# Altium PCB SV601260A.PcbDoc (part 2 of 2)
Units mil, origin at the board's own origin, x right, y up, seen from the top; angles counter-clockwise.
Board outline 2250 x 2132 mil, 4 copper layers (Top Layer, GND, POWER, Bottom Layer), stack 59.6 mil thick; 105 components, 61 nets, 262 pads, 157 vias.
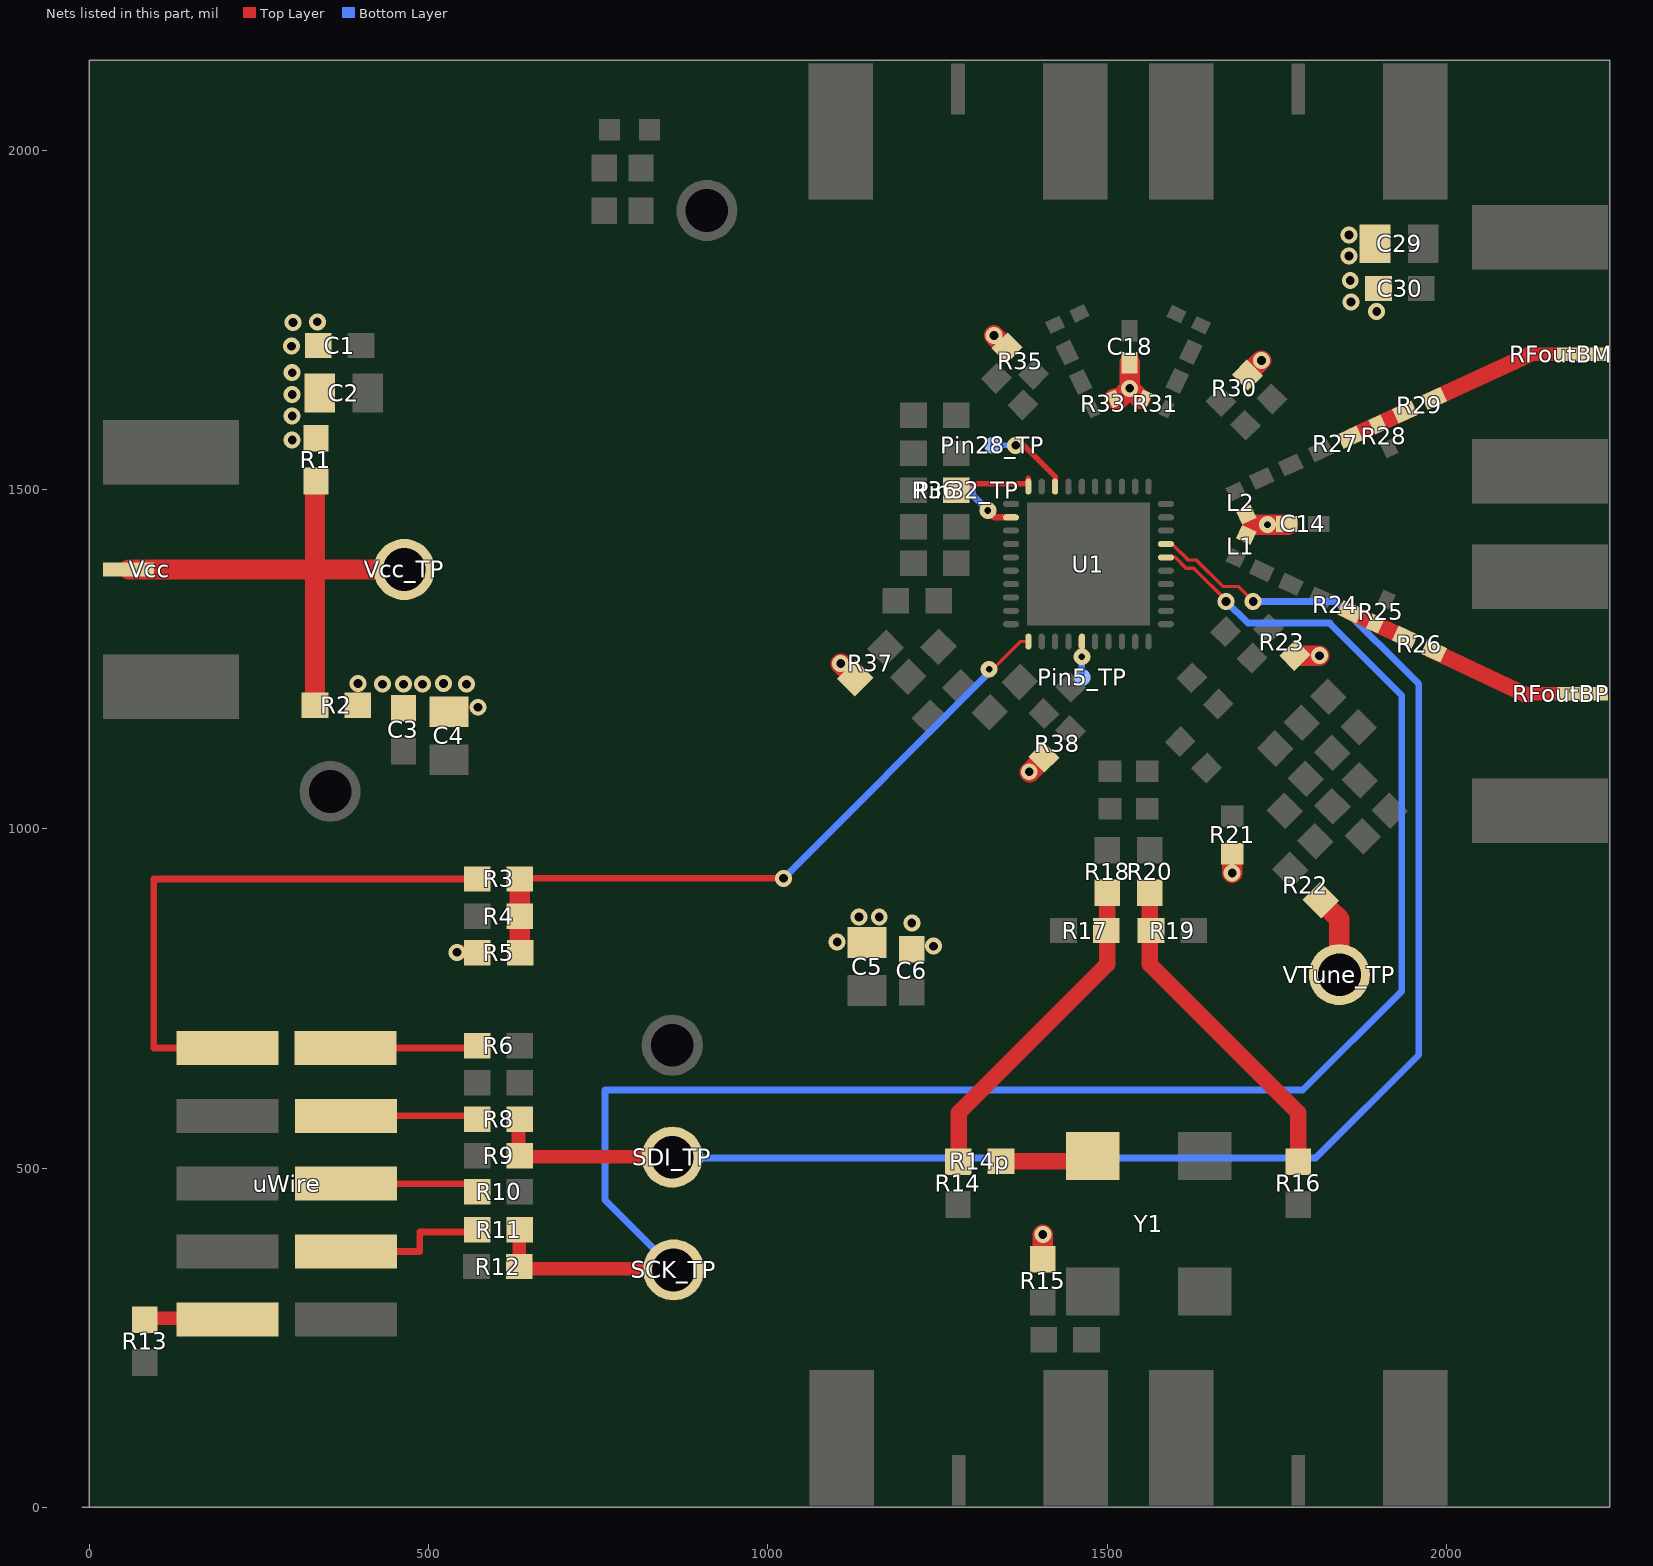
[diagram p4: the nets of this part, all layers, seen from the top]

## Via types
v1: diameter 25, hole 13, Top Layer to Bottom Layer, tented both sides, 74 vias
v2: diameter 25, hole 13, Top Layer to Bottom Layer, 65 vias
v3: diameter 19.68, hole 7.87, Top Layer to Bottom Layer, 12 vias
v4: diameter 25, hole 10, Top Layer to Bottom Layer, 6 vias

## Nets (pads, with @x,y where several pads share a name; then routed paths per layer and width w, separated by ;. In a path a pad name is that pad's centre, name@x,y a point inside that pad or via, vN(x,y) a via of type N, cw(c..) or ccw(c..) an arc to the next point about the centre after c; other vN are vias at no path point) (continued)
NetPin5_TP_1: Pin5_TP.1 U1.5 | length 46.4
  Top Layer w10: v4(1462.44,1253.44) U1.5@1462.44,1275.83
  Bottom Layer w10: Pin5_TP.1@1462.44,1229.44 v4(1462.44,1253.44)
NetPin28_TP_1: Pin28_TP.1 U1.28 | length 125.9
  Top Layer w8: v1(1365,1565) 1377,1565 1423.07,1518.93 U1.28@1423.07,1504.17
  Bottom Layer w8: Pin28_TP.1@1331,1565 v1(1365,1565)
NetPin32_TP_1: Pin32_TP.1 U1.32 | length 80.7
  Top Layer w10: v4(1324,1469) 1334.1,1458.9 U1.32@1358.11,1458.9
  Bottom Layer w10: Pin32_TP.1@1294,1499 v4(1324,1469)
NetR1_1: R1.1 R2.1 Vcc.1 Vcc_TP.1 | length 735
  Top Layer w30: Vcc.1@58,1382 332.5,1382 ; R2.1@332.5,1182 332.5,1382 ; R1.1@332.5,1511.01 332.5,1382 ; Vcc_TP.1@464,1382 332.5,1382
NetR3_1: R3.1 uWire.1 | length 833
  Top Layer w10: 95,677 uWire.1@203.5,677 ; 95,678 95,926 R3.1@571.5,926
NetR3_2: R3.2 R4.2 R5.2 U1.1 | length 1005.3
  Top Layer w5: v4(1326,1235) 1331,1235 1371.83,1275.83 U1.1@1383.7,1275.83 U1.1@1383.53,1276
  Top Layer w10: R3.2@634.5,926 635.5,927 v2(1023,927)
  Top Layer w30: R5.2@634.5,818 R4.2@634.5,871 R3.2@634.5,926
  Bottom Layer w10: v2(1023,927) 1326,1230 v4(1326,1235)
NetR6_1: R6.1 uWire.2 | length 194
  Top Layer w10: uWire.2@377.5,677 R6.1@571.5,677
NetR8_1: R8.1 R9.2 SDI_TP.1 U1.17 | length 2427.2
  Top Layer w5: U1.17@1586.46,1419.53 1595.47,1419.53 1619,1396 1631.4,1396 1670.4,1357 1693,1357 v1(1715,1335)
  Top Layer w20: 632.5,553 632.5,517 826,517 SDI_TP.1@844,499
  Bottom Layer w10: SDI_TP.1@860,500 875,515 1807,515 1959,667 1959,1213 1837,1335 v1(1715,1335)
NetR8_2: R8.2 uWire.4 | length 192
  Top Layer w10: uWire.4@378.5,577 R8.2@570.5,577
NetR10_2: R10.2 uWire.6 | length 202.5
  Top Layer w10: uWire.6@378.5,477 R10.2@581,477
NetR11_1: R11.1 uWire.8 | length 222
  Top Layer w10: uWire.8@378.5,377 487,377 487,406 R11.1@571.5,406
NetR11_2: R11.2 R12.2 SCK_TP.1 U1.16 | length 2691.2
  Top Layer w5: U1.16@1586.46,1399.84 1600.16,1399.84 1616,1384 1627.3,1384 1675,1336.3 v1(1675,1335)
  Top Layer w20: R11.2@634.5,409 633.5,408 R12.2@633.5,355 636.5,352 SCK_TP.1@861,352
  Bottom Layer w10: SCK_TP.1@861,352 760,453 760,615 1788,615 1934,761 1934,1196 1827,1303 ; v1(1675,1335) 1707,1303 1828,1303
NetR13_1: R13.1 uWire.9 | length 107.5
  Top Layer w20: R13.1@82,278.91 uWire.9@189.5,278.41
NetR14_2: R14.2 R14p.1 R17.1 R18.1 | length 485.2
  Top Layer w24: R14p.1@1281.34,510.83 1281.34,581.66 1500,800.32 R18.1@1500,905.5
NetR14p_2: R14p.2 Y1.3 | length 138.1
  Top Layer w24: R14p.2@1343.5,510 1470.32,510 Y1.3@1478.32,518
NetR16_2: R16.2 R19.2 R20.2 | length 485.2
  Top Layer w24: R20.2@1562.68,905.5 1562.68,800.32 1781.34,581.66 R16.2@1781.34,510.83
NetR22_2: R22.2 VTune_TP.1 | length 98.5
  Top Layer w30: 1830.31,878.69 1842,867 VTune_TP.1@1842,785
NetR24_1: R24.1 R25.2 R26.2 | length 85.5
  Top Layer w24: R24.1@1855,1321 R26.2@1932.37,1284.51
NetR26_1: R26.1 RFoutBP.1 | length 235.1
  Top Layer w20: 2118.03,1199.06 RFoutBP.1@2200,1199.06
  Top Layer w24: R26.1@1978.06,1262.84 1981.12,1261.39 2116.51,1197.54
NetR27_1: R27.1 R28.1 R29.2 | length 85.5
  Top Layer w24: R27.1@1860,1578 R29.2@1937.68,1613.81
NetR29_1: R29.1 RFoutBM.1 | length 229.8
  Top Layer w20: 2123.25,1699.06 RFoutBM.1@2200,1699.06
  Top Layer w24: R29.1@1981.41,1633.98 2120.43,1698.07
NetR36_1: R36.1 U1.30 | length 105.8
  Top Layer w8: R36.1@1286,1508.17 1383.7,1508.17 1383.7,1516.3
VCC: C3.2 C4.2 C5.2 C6.2 R2.2 R5.1 R15.2 R21.1 R23.1 R35.2 R37.2 R38.1 | length 192.7
  Top Layer w20: v2(542,818) R5.1@571.5,818
  Top Layer w30: v1(1107.16,1243.3) R37.2@1128.73,1221.73 ; v1(1333,1727) R35.2@1351.51,1708.49 ; v1@1385.5,1083.5 R38.1@1404.46,1102.46 ; R15.2@1405,365.5 v2(1405,402) ; v1(1684,935) v1@1684,944.69 ; R23.1@1779,1255 v2(1812.5,1255)
  other v1: 1385,1084 463,1213 556,1213 396,1214 522,1214
  other v2: 1244,827 1102,833 1212,861 1134,870 1164,870 573,1179 432,1213 491,1213
VCCRF: C1.2 C2.2 C14.2 C18.2 C29.2 C30.2 L1.2 L2.2 R1.2 R30.1 R31.2 R33.1 | length 170.4
  Top Layer w30: R33.1@1510.06,1633.49 1517.49,1633.49 v2(1533,1649) ; C18.2@1533,1686.38 v2(1533,1649) ; R31.2@1548.51,1633.49 v2(1533,1649) ; R30.1@1705.99,1668.99 v1(1727,1690) ; 1714,1448 C14.2@1766,1448
  other v1: 299,1573 299,1608 299,1640 298,1711
  other v2: 299,1672 300,1746 336,1747 1897,1762 1859,1776 1858,1808 1856,1844 1856,1875
  other v4: 1736,1448
pads on no net: uWire.5 uWire.7 uWire.10 Y1.1

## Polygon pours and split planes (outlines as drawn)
GND on Top Layer "Top Layer-No Net 1" (solid, pour order 11): 1943,1888.52 1944,1887.36 1944,1746 2023,1746 2019,1750.64 2019,1890.84 1944,1890.84 1943,1892
VCCRF on Top Layer "Top Layer-No Net 1" (solid, pour order 10): 1840,1888.55 1841.01,1887.4 1841.01,1747 1921,1747 1916.95,1751.6 1916.95,1890.85 1841.01,1890.85 1840,1892
GND on Top Layer "Top Layer-No Net 2" (solid, pour order 13): 1088,784 1261,784 1261,715.06 1258.49,713 1090.51,713 1088,715.06 1088,781.94
VCC on Top Layer "Top Layer-No Net 2" (solid, pour order 12): 1088,884 1258,884 1258,812.14 1255.54,810 1090.46,810 1088,812.14 1088,881.86
VCCRF on Top Layer "Top Layer-No Net 3" (solid, pour order 14): 362,1557.2 287,1557.2 286,1556 276,1567.97 276,1763 356,1763 358,1760.61 362,1755.82 362,1558.39
GND on Top Layer "Top Layer-No Net 4" (solid, pour order 15): 381,1761 381,1616.85 383,1614.32 388,1608 465,1608 465,1761 381,1761
GND on Top Layer "Top Layer-No Net" (solid, pour order 17): 557,1133 305,1133 309,1129 309,1000 561,1000 560,1001 560,1133 556,1133 555,1132
VCC on Top Layer "Top Layer-No Net 5" (solid, pour order 18): 582.56,1151 377.29,1151 376.15,1150 376.15,1226 375,1227 586,1227 586,1150
GND on Top Layer "VCOGND" (solid, pour order 16): 1301,1713 1088,1713 999,1624 999,1170 1115,1054 1232,1054 1235,1054 1334,1153 1296,1191 1252,1191 1252,1192 1199.5,1244.5 1167,1212 1167,1211 1167,1187 1122,1142 1056,1208 1056,1244 1130,1318 1208,1318 1208,1357 1223,1372 1233,1372 1233,1645 1334,1645 1335,1646 1336,1647 1336,1678 1301,1713
GND on GND (split plane): 2239.95,0.05 0.05,0.05 0.05,2131.95 2239.95,2131.95
VCCRF on POWER (split plane): 2219.9,1280.09 2069.18,1280.09 1957.13,1392.13 1952.13,1397.13 1950.04,1398.74 1947.61,1399.74 1945,1400.09 1734.18,1400.09 1701.09,1433.18 1701.09,1539 1700.74,1541.61 1700.03,1543.33 1699.74,1544.04 1698.13,1546.13 1657.13,1587.13 1655.04,1588.74 1652.61,1589.74 1650,1590.09 1564.18,1590.09 1457.13,1697.13 1232.13,1922.13 1230.04,1923.73 1227.61,1924.74 1225,1925.09 710,1925.09 707.39,1924.74 706.17,1924.24 704.96,1923.73 702.87,1922.13 637.87,1857.13 636.27,1855.04 635.26,1852.61 634.91,1850 634.91,1795 634.91,1760 634.91,1609.18 616.87,1591.13 612.87,1587.13 577.82,1552.09 20.1,1552.09 20.1,2111.9 2219.9,2111.9
VCC on POWER (split plane): 1442.87,1682.87 1552.87,1572.87 1554.96,1571.26 1557.39,1570.26 1560,1569.91 1645.82,1569.91 1680.91,1534.82 1680.91,1429 1681.26,1426.39 1682.26,1423.96 1683.87,1421.87 1722.87,1382.87 1724.96,1381.26 1726.68,1380.55 1727.39,1380.26 1730,1379.91 1940.82,1379.91 1942.87,1377.87 2057.87,1262.87 2059.96,1261.26 2060.67,1260.97 2062.39,1260.26 2065,1259.91 2219.9,1259.91 2219.9,20.1 20.1,20.1 20.1,1531.91 582,1531.91 584.61,1532.26 587.04,1533.26 589.13,1534.87 631.13,1576.87 652.13,1597.87 653.73,1599.96 654.45,1601.68 654.74,1602.39 655.09,1605 655.09,1760 655.09,1795 655.09,1845.82 714.18,1904.91 1220.82,1904.91

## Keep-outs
Keep-Out Layer:
  lines w1: 0,0 2238,0 2240,0 2240,2132 0,2132 0,195 ; 0,0 0,195 ; 0,0 0,195
  text ".Layer_Name" at 327,-1618.49 h60

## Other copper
Top Layer:
  text ".Layer_Name" at 327,-1618.49 h60
Bottom Layer:
  text ".Layer_Name" at 327,-1618.49 h60
POWER (plane layer: these items are gaps in the copper):
  lines w20: 0,1542 465,1542 ; 462,1542 582,1542 624,1584 ; 620,1580 645,1605 645,1760 645,1795 645,1850 710,1915 1070,1915 1120,1915 ; 1110,1915 1225,1915 1450,1690 1560,1580 1650,1580 1691,1539 1691,1429 1730,1390 1945,1390 1950,1385 2065,1270 2100,1270 2236,1270

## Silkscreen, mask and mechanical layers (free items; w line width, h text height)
Top Overlay:
  circle w20: c1311.93,1264 r7.07
  region: 84,2015 34,2015 34,1963 84,1963
  region: 85,2093 35,2093 35,2041 85,2041
  region: 371,1880 254,1880 254,1828 371,1828
  lines w5: 91.5,513.5 121.68,543.68 ; 109.68,543.68 121.68,543.68 ; 121.68,528.32 121.68,543.68
  text "LMX2582EVM" at 105,2040 h60
  text "LMX2592EVM" at 104,1959 h60
  text "12-18-2015" at 79,1904 h25
  text "Board #" at 51,1851 h25
  text "CE" at 61,678 h25
  text "MUXout" at 57,592 h25 r270
  text ".Layer_Name" at 327,-1618.49 h60
Bottom Overlay:
  rectangle: 413,33 713,133
  text "Rev A" at 970,120 h25
  text "SV601260-" at 983,67 h30
  text ".Layer_Name" at 327,-1618.49 h60
Top Paste:
  text ".Layer_Name" at 327,-1618.49 h60
Bottom Paste:
  text ".Layer_Name" at 327,-1618.49 h60
Top Solder:
  lines w40: 1278,2052 1278,2121 ; 1279.12,2048.59 1511.99,1549.18 ; 1530.45,1507.2 1530.45,1541.2 ; 1552.27,1551.77 1779.49,2039.04 ; 1609.94,1465.12 2117.3,1699.1 ; 1610.68,1431.48 2116.4,1200 ; 1783,2047 1783,2116 ; 2115,1200 2233,1200 ; 2120,1700 2236,1700
  text ".Layer_Name" at 327,-1618.49 h60
  text ".Layer_Name" at 327,-1618.49 h60
Bottom Solder:
  text ".Layer_Name" at 327,-1618.49 h60
Drill Guide:
  text ".Layer_Name" at 327,-1618.49 h60
M1 Board Outline:
  lines w5: -1,0 2239,0 ; -1,2131 2240,2131 2240,0
  text ".Layer_Name" at 327,-1618.49 h60
M2 Board Dimensions:
  rectangle: -125.5,-1170.5 249.5,-1045.5
  rectangle: -250.5,-1045.5 -125.5,-920.5
  lines w7: -250.5,-1045.5 749.5,-1045.5 ; -125.5,-1170.5 -125.5,-920.5 ; -0.5,-1170.5 -0.5,-920.5 ; 249.5,-1170.5 249.5,-920.5 ; 499.5,-1170.5 499.5,-920.5 ; -250.5,-1170.5 -250.5,-920.5 749.5,-920.5 749.5,-1170.5 -250.5,-1170.5
  lines w10: -250.5,-1235.5 -250.5,-1215.5 ; -190.5,-1245.5 -250.5,-1225.5 ; -190.5,-1205.5 -250.5,-1225.5 ; -26.42,-1225.5 -250.5,-1225.5 ; 525.42,-1225.5 749.5,-1225.5 ; 689.5,-1245.5 749.5,-1225.5 ; 689.5,-1205.5 749.5,-1225.5 ; 749.5,-1235.5 749.5,-1215.5
  text "1000 (mil)" at -16.42,-1261.49 h60
  text ".Layer_Name" at 327,-1618.49 h60
M3 3D STEP Top:
  text ".Layer_Name" at 327,-1618.49 h60
M4 3D STEP Bottom:
  text ".Layer_Name" at 327,-1618.49 h60
M5 Assembly Top:
  lines w10: -542,-1690.17 6058,-1690.17 ; -542,-1486.83 6060,-1486.83 ; -542,-1283.5 -542,-1893.5 3463,-1893.5 6060,-1893.5 6060,-1283.5 -541.5,-1283.5 -541.5,-1893.5 1034,-1893.5 ; 1923,-1893.5 1923,-1283.5 ; 3190,-1486.83 3190,-1283.5 ; 4030,-1486.83 4030,-1283.5 ; 4652,-1900 4652,-1697.17
  text "COMPONENTS MARKED 'DNP' SHOULD NOT BE POPULATED." at 903.5,-1078.5 h20
  text "ASSEMBLY VARIANT:" at 903,-1194 h20
  text ".VariantName" at 1939,-1194 h20
  text "PCB VIEWED FROM TOP SIDE" at -478.5,-1415.67 h60
  text "BOARD #:" at 1998,-1415.67 h60
  text ".PRJ_Number" at 2543.5,-1415.67 h60
  text "REV:" at 3388,-1415.67 h60
  text ".PCB_Rev" at 3679.5,-1415.67 h60
  text "SVN REV:" at 4226,-1415.67 h60
  text ".VersionControl_RevNumber" at 4732,-1415.67 h60
  text "TID #:" at 1998,-1619 h60
  text ".TID" at 2543.5,-1619 h60
  text "PLOT NAME =" at -478.5,-1824.34 h60
  text ".plot_File_Name" at 327,-1824.34 h60
  text "GENERATED    :" at 2000,-1824.34 h60
  text ".Print_Date" at 2869.5,-1824.34 h60
  text ".Print_Time" at 3598.5,-1824.34 h60
  text "TEXAS INSTRUMENTS" at 4863,-1824.34 h60
M6 Assembly Bottom:
  lines w10: -542.5,-1487.33 6059.5,-1487.33 ; -540.5,-1690.67 6059.5,-1690.67 ; 865.5,-1900.5 865.5,-1697.67 ; 1487.5,-1487.33 1487.5,-1284 ; 2327.5,-1487.33 2327.5,-1284 ; 3594.5,-1894 3594.5,-1284 ; 4483.5,-1894 6059,-1894 6059,-1284 -542.5,-1284 -542.5,-1894 2054.5,-1894 6059.5,-1894 6059.5,-1284
  text "COMPONENTS MARKED 'DNP' SHOULD NOT BE POPULATED." at 5852,-1078 h30
  text ".VariantName" at 4808,-1194 h30
  text "ASSEMBLY VARIANT:" at 5847,-1194 h30
  text ".VersionControl_RevNumber" at 785.5,-1416.17 h60
  text "SVN REV:" at 1291.5,-1416.17 h60
  text ".PCB_Rev" at 1838,-1416.17 h60
  text "REV:" at 2129.5,-1416.17 h60
  text ".PRJ_Number" at 2974,-1416.17 h60
  text "BOARD #:" at 3519.5,-1416.17 h60
  text "PCB VIEWED FROM BOTTOM SIDE" at 5996,-1416.17 h60
  text ".TID" at 2974,-1619.5 h60
  text "TID #:" at 3519.5,-1619.5 h60
  text "TEXAS INSTRUMENTS" at 654.5,-1824.84 h60
  text ".Print_Time" at 1919,-1824.84 h60
  text ".Print_Date" at 2648,-1824.84 h60
  text "GENERATED    :" at 3517.5,-1824.84 h60
  text ".plot_File_Name" at 5190.5,-1824.84 h60
  text "PLOT NAME =" at 5996,-1824.84 h60
M9 Title Sheet:
  drawing of 57 lines, arcs and shapes, not listed
  text "1" at 489.84,7276.5 h70
  text "2" at 2985.5,7276.5 h70
  text "3" at 5474.84,7276.5 h70
  text "4" at 7981.51,7276.5 h70
  text "5" at 10480.5,7276.5 h70
  text "6" at 12985.5,7276.5 h70
  text "A" at -666.5,6133.5 h70
  text "A" at 14133.5,6133.5 h70
  text "B" at -666.5,3753.5 h70
  text "B" at 14133.5,3753.5 h70
  text "C" at -666.5,1378.5 h70
  text "C" at 14133.5,1378.5 h70
  text "PROJECT TITLE:" at 11093.5,-482.5 h45
  text ".PRJ_Title" at 11143.5,-615.83 h70
  text "DESIGNED FOR:" at 11093.5,-783.5 h45
  text ".PRJ_Customer" at 11143.5,-923.5 h70
  text "D" at -666.5,-991.5 h70
  text "D" at 14133.5,-991.5 h70
  text "FILE NAME:" at 11093.5,-1083.5 h45
  text ".PCB_File_Name_No_Path" at 11143.5,-1203.5 h70
  text "Texas Instruments (TI) and/or its licensors do not warrant the accuracy or completeness of this specification" at 6124,-1365.34 h45
  text "ENGINEER:" at 11093.5,-1373.5 h45
  text "LAYOUT BY:" at 12598.5,-1373.5 h45
  text "or any information contained therein. TI and/or its licensors do not warrant that this design will meet" at 6079.01,-1478 h45
  text ".PRJ_Engineer" at 11143.5,-1528.49 h70
  text ".PCB_Layout" at 12649,-1528.49 h70
  text "the specifications, will be suitable for your application or fit for any particular purpose, or will operate in" at 6079.01,-1590.67 h45
  text ".Layer_Name" at 327,-1618.49 h60
  text "ALTIUM DESIGNER VERSION:" at 12598.5,-1683.5 h45
  text "an implementation. TI and/or its licensors do not warrant that the design is production worthy. You should" at 6079.01,-1703.33 h45
  text "completely validate and test your design implementation to confirm the system functionality for your application." at 6124,-1816 h45
  text ".print_Scale" at 11143.5,-1816.83 h70
  text ".Application_BuildNumber" at 12649,-1816.83 h70
  text "1" at 489.84,-2023.5 h70
  text "2" at 2985.5,-2023.5 h70
  text "3" at 5474.84,-2023.5 h70
  text "4" at 7981.51,-2023.5 h70
  text "5" at 10480.5,-2023.5 h70
  text "6" at 12985.5,-2023.5 h70
M10 Fab Notes:
  drawing of 214 lines, arcs and shapes, not listed
  text "DESIGN INFORMATION" at 12134.02,6047 h60
  text "(REFER ALSO ARRAY/PANEL PROFILING INFORMATION)" at 11772.46,5885.29 h60
  text "BOARD SIZE" at 11086.46,5881 h60
  text "2450MIL" at 11548.78,5753.18 h60
  text "X" at 12054.46,5753.18 h60
  text "2700MIL" at 12285.78,5753.18 h60
  text "Number of Layers :" at 11489.46,5556 h60
  text "4" at 12584.27,5546 h60
  text "20mils width on top layer should be controlled 50 ohms +/- 5%" at 4866,5502 h100
  text "MIN. TRACK WIDTH:" at 11489.46,5417 h60
  text "5" at 12585.7,5417 h60
  text "MIL" at 12740.46,5417 h60
  text "MIN. CLEARANCE:" at 11489.46,5285 h60
  text "5" at 12585.7,5285 h60
  text "MIL" at 12740.46,5285 h60
  text "MIN. VIA PAD SIZE:" at 11489.46,5153 h60
  text "25" at 12555.71,5153 h60
  text "MIL" at 12740.46,5153 h60
  text "0.05mm (2MIL)" at 12184.46,5011.29 h60
  text "MINIMUM ANNULAR RING" at 11160.23,5007 h60
  text "EXTERNAL" at 12892.46,5007 h60
  text "PER" at 11360.23,4889 h60
  text "IPC-D-275 CLASS 2 LEVEL C" at 11580.23,4889 h60
  text "MIL, HOLES" at 13068.46,4776.71 h60
  text "+/-" at 12676,4776 h60
  text "+/-" at 13530,4776 h60
  text "REGISTRATION TOLERANCES:" at 11160.23,4771 h60
  text "METAL" at 12360,4771 h60
  text "5" at 12936.2,4771 h60
  text "3" at 13769.2,4771 h60
  text "MIL" at 13885.46,4771 h60
  text "MATERIAL:" at 11125.46,4631.54 h60
  text "FR4 High Tg" at 12111.9,4491.21 h60
  text "X" at 12851,4484 h60
  text "FR-408" at 11546.46,4482.64 h60
  text "RO4003C" at 13034.46,4482.64 h60
  text "62 MIL (1.6mm) +/-10%" at 11866.56,4319.92 h60
  text "THICKNESS:" at 11200.23,4315.64 h60
  text "X" at 11738.4,4315.64 h60
  text "OTHER" at 13151.46,4315.64 h60
  text "TOLERANCE:" at 11200.23,4157.64 h60
  text "X" at 12039.53,4157.64 h60
  text "ANSI IPC-6012 TYPE 3 CLASS 2" at 12226.48,4157.64 h60
  text "OTHER +/-" at 12226.46,4001.64 h60
  text "BOW & TWIST:" at 11200.23,3844.64 h60
  text "X" at 12039.53,3844.64 h60
  text "ANSI IPC-6012 TYPE 3 CLASS 2" at 12226.48,3844.64 h60
  text "OTHER +/-" at 12226.46,3686.13 h60
  text "COPPER THICKNESS (FINISHED):" at 11125.46,3550.64 h60
  text "1.4MIL (1oz)" at 12005.46,3397.92 h60
  text "2MIL (1.4oz)" at 12772.46,3397.92 h60
  text "2.8MIL (2oz)" at 13499.46,3397.92 h60
  text "OUTER:" at 11482.46,3393.64 h60
  text "X" at 11877,3393 h60
  text "1.4MIL (1oz)" at 12005.46,3240.92 h60
  text "2.8MIL (2oz)" at 12772.46,3240.92 h60
  text "N/A" at 13499,3241.29 h60
  text "INNER SIGNAL:" at 11193.38,3236.64 h60
  text "X" at 11878.42,3236.64 h60
  text "DRILLING:" at 11125.46,3097.64 h60
  text "REFERENCE:" at 11200.23,2980.64 h60
  text "X" at 11848.46,2980.64 h60
  text "AS SHOWN" at 12035.46,2980.64 h60
  text "X" at 12749.46,2980.64 h60
  text "NC_DRILL FILES" at 12886.46,2980.64 h60
  text "PTH MIN COPPER THICKNESS:" at 11200.23,2822.64 h60
  text "X" at 12550.46,2822.64 h60
  text "1MIL" at 12687.46,2822.64 h60
  text "OTHER" at 13184.46,2822.64 h60
  text "BOARD FINISH:" at 11125.46,2663.64 h60
  text "SILKSCREEN:" at 11280.68,2545.64 h60
  text "X" at 12229.46,2545.64 h60
  text "TOP" at 12355.46,2545.64 h60
  text "X" at 12739.46,2545.64 h60
  text "BOTTOM" at 12866.46,2545.64 h60
  text "SILKSCREEN COLOR:" at 11280.68,2378.64 h60
  text "X" at 12228.42,2378.64 h60
  text "WHITE" at 12355.46,2378.64 h60
  text "OTHER" at 12866.46,2378.64 h60
  text "SOLDER RESIST COLOR:" at 11280.68,2208.64 h60
  text "X" at 11833.42,2069.44 h60
  text "GREEN" at 11960.46,2069.44 h60
  text "BLUE" at 12551.46,2069.44 h60
  text "OTHER" at 13089.46,2069.44 h60
  text "IMMERSION GOLD (ENIG)" at 12176.46,1915.92 h60
  text "ENEPIG" at 13514,1912.64 h60
  text "SURFACE FINISH:" at 11115.46,1911.64 h60
  text "X" at 11989.51,1911.64 h60
  text "IMM. TIN/SILVER OR EQUIV" at 11445,1754.64 h60
  text "OTHER" at 12876.46,1754.64 h60
  text "ARRAY/PANEL:" at 11115.46,1575.64 h60
  text "CUT AND TRIM PER MECH LAYER 1" at 12176.46,1571.35 h60
  text "N.C. ROUTE" at 12176.46,1419.64 h60
  text "X" at 12855.46,1419.64 h60
  text "V. SCORE" at 13042.46,1419.64 h60
  text "CERTIFICATION:" at 11115.46,1282.64 h60
  text "MATERIALS AND WORKMANSHIP FOR ALL PCBS" at 11840.46,1282.64 h60
  text "TO MEET OR EXCEED THE REQUIREMENTS OF:" at 11840.46,1184.64 h60
  text "X" at 11466.96,1048.13 h60
  text "ANSI IPC-A-600F CLASS ->" at 11605.96,1048.13 h60
  text "X" at 13245.02,1048.13 h60
  text "2" at 13363.96,1048.14 h60
  text "1" at 13048.96,1046.64 h60
  text "3" at 13717.96,1046.64 h60
  text "X" at 11469.02,888.64 h60
  text "UL 94V-0" at 11605.96,888.64 h60
  text "X" at 12281.02,888.64 h60
  text "RoHS" at 12417.96,888.64 h60
  text "OTHER" at 13062.36,888.64 h60
  text "PER ORDER" at 13459.42,888.64 h60
  text "ADDITIONAL REQUIREMENTS:" at 11115.46,732.64 h60
  text "MICROSECTION:" at 11200.23,602.64 h60
  text "YES" at 12105.96,602.64 h60
  text "REQUIRED" at 12967.46,476.49 h60
  text "BARE BOARD ELEC. TEST:" at 11200.23,473.64 h60
  text "NONE" at 12505.96,473.64 h60
  text "X" at 12840.46,473.64 h60
  text "PER ORDER" at 13559.46,473.64 h60
  text "MANUFACTURER'S UL:" at 11200.23,316.64 h60
  text "RAIL" at 12365.96,312.35 h60
  text "METAL" at 12857.77,312.35 h60
  text "X" at 13233,312 h60
  text "SILK" at 13369.46,312.35 h60
  text "Note: Not put solder on U1 (LMX2592 IC) footprint if IC is not installed." at 11095,175 h42
  text ".Layer_Name" at 327,-1618.49 h60
M11 Gerber Information:
  lines w10: -542,-1690.17 6058,-1690.17 ; -542,-1486.83 6060,-1486.83 ; -542,-1283.5 -542,-1893.5 3463,-1893.5 6060,-1893.5 6060,-1283.5 -541.5,-1283.5 -541.5,-1893.5 1034,-1893.5 ; 1923,-1893.5 1923,-1283.5 ; 3190,-1486.83 3190,-1283.5 ; 4030,-1486.83 4030,-1283.5 ; 4652,-1900 4652,-1697.17
  text "ALL ARTWORK VIEWED FROM TOP SIDE" at -478.5,-1415.67 h60
  text "BOARD #:" at 1998,-1415.67 h60
  text ".PRJ_Number" at 2543.5,-1415.67 h60
  text "REV:" at 3388,-1415.67 h60
  text ".PCB_Rev" at 3679.5,-1415.67 h60
  text "SVN REV:" at 4226,-1415.67 h60
  text ".VersionControl_RevNumber" at 4732,-1415.67 h60
  text "LAYER NAME =" at -478.5,-1618.49 h60
  text "TID #:" at 1998,-1619 h60
  text ".TID" at 2543.5,-1619 h60
  text "PLOT NAME =" at -478.5,-1824.34 h60
  text ".plot_File_Name" at 327,-1824.34 h60
  text "GENERATED    :" at 2000,-1824.34 h60
  text ".Print_Date" at 2869.5,-1824.34 h60
  text ".Print_Time" at 3598.5,-1824.34 h60
  text "TEXAS INSTRUMENTS" at 4863,-1824.34 h60
M12 Stackup:
  drawing of 295 lines, arcs and shapes, not listed
  text "Layer" at 2762.74,2773 h60
  text "Name" at 3172.65,2773 h60
  text "Material" at 4102.4,2773 h60
  text "Thickness" at 4962.16,2773 h60
  text "Constant" at 5612,2773 h60
  text "Board Layer Stack" at 6181.86,2773 h60
  text "1" at 2762.74,2653 h60
  text "Top Overlay" at 3172.65,2653 h60
  text "2" at 2762.74,2533 h60
  text "Top Solder" at 3172.65,2533 h60
  text "Solder Resist" at 4102.4,2533 h60
  text "0.40mil" at 4962.16,2533 h60
  text "3.5" at 5612,2533 h60
  text "3" at 2762.74,2413 h60
  text "Top Layer" at 3172.65,2413 h60
  text "Copper" at 4102.4,2413 h60
  text "1.40mil" at 4962.16,2413 h60
  text "4" at 2762.74,2293 h60
  text "Dielectric1" at 3172.65,2293 h60
  text "Rogers4003C" at 4102.4,2293 h60
  text "9.50mil" at 4962.16,2293 h60
  text "4.8" at 5612,2293 h60
  text "5" at 2762.74,2173 h60
  text "GND" at 3172.65,2173 h60
  text "Copper" at 4102.4,2173 h60
  text "1.40mil" at 4962.16,2173 h60
  text "6" at 2762.74,2053 h60
  text "Dielectric2" at 3172.65,2053 h60
  text "FR-4" at 4102.4,2053 h60
  text "35.00mil" at 4962.16,2053 h60
  text "4.8" at 5612,2053 h60
  text "7" at 2762.74,1933 h60
  text "POWER" at 3172.65,1933 h60
  text "Copper" at 4102.4,1933 h60
  text "1.40mil" at 4962.16,1933 h60
  text "8" at 2762.74,1813 h60
  text "Dielectric3" at 3172.65,1813 h60
  text "FR-4" at 4102.4,1813 h60
  text "9.50mil" at 4962.16,1813 h60
  text "4.8" at 5612,1813 h60
  text "9" at 2762.74,1693 h60
  text "Bottom Layer" at 3172.65,1693 h60
  text "Copper" at 4102.4,1693 h60
  text "1.40mil" at 4962.16,1693 h60
  text "10" at 2762.74,1573 h60
  text "Bottom Solder" at 3172.65,1573 h60
  text "Solder Resist" at 4102.4,1573 h60
  text "0.40mil" at 4962.16,1573 h60
  text "3.5" at 5612,1573 h60
  text "11" at 2762.74,1453 h60
  text "Bottom Overlay" at 3172.65,1453 h60
  text ".Layer_Name" at 327,-1618.49 h60
M13 Component Bodies Top:
  text ".Layer_Name" at 327,-1618.49 h60
M14 Component Bodies Bottom:
  text ".Layer_Name" at 327,-1618.49 h60
M15 Courtyards Top:
  text ".Layer_Name" at 327,-1618.49 h60
M16 Courtyards Bottom:
  text ".Layer_Name" at 327,-1618.49 h60
Drill Drawing:
  text ".legend" at 5752,-131 h30
  text "Drill Table" at 5730,-395 h30
  text ".Layer_Name" at 327,-1618.49 h60

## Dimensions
0.44,-33 to 2237.44,-30 on M2 Board Dimensions
2284,0 to 2530,2131 on M2 Board Dimensions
